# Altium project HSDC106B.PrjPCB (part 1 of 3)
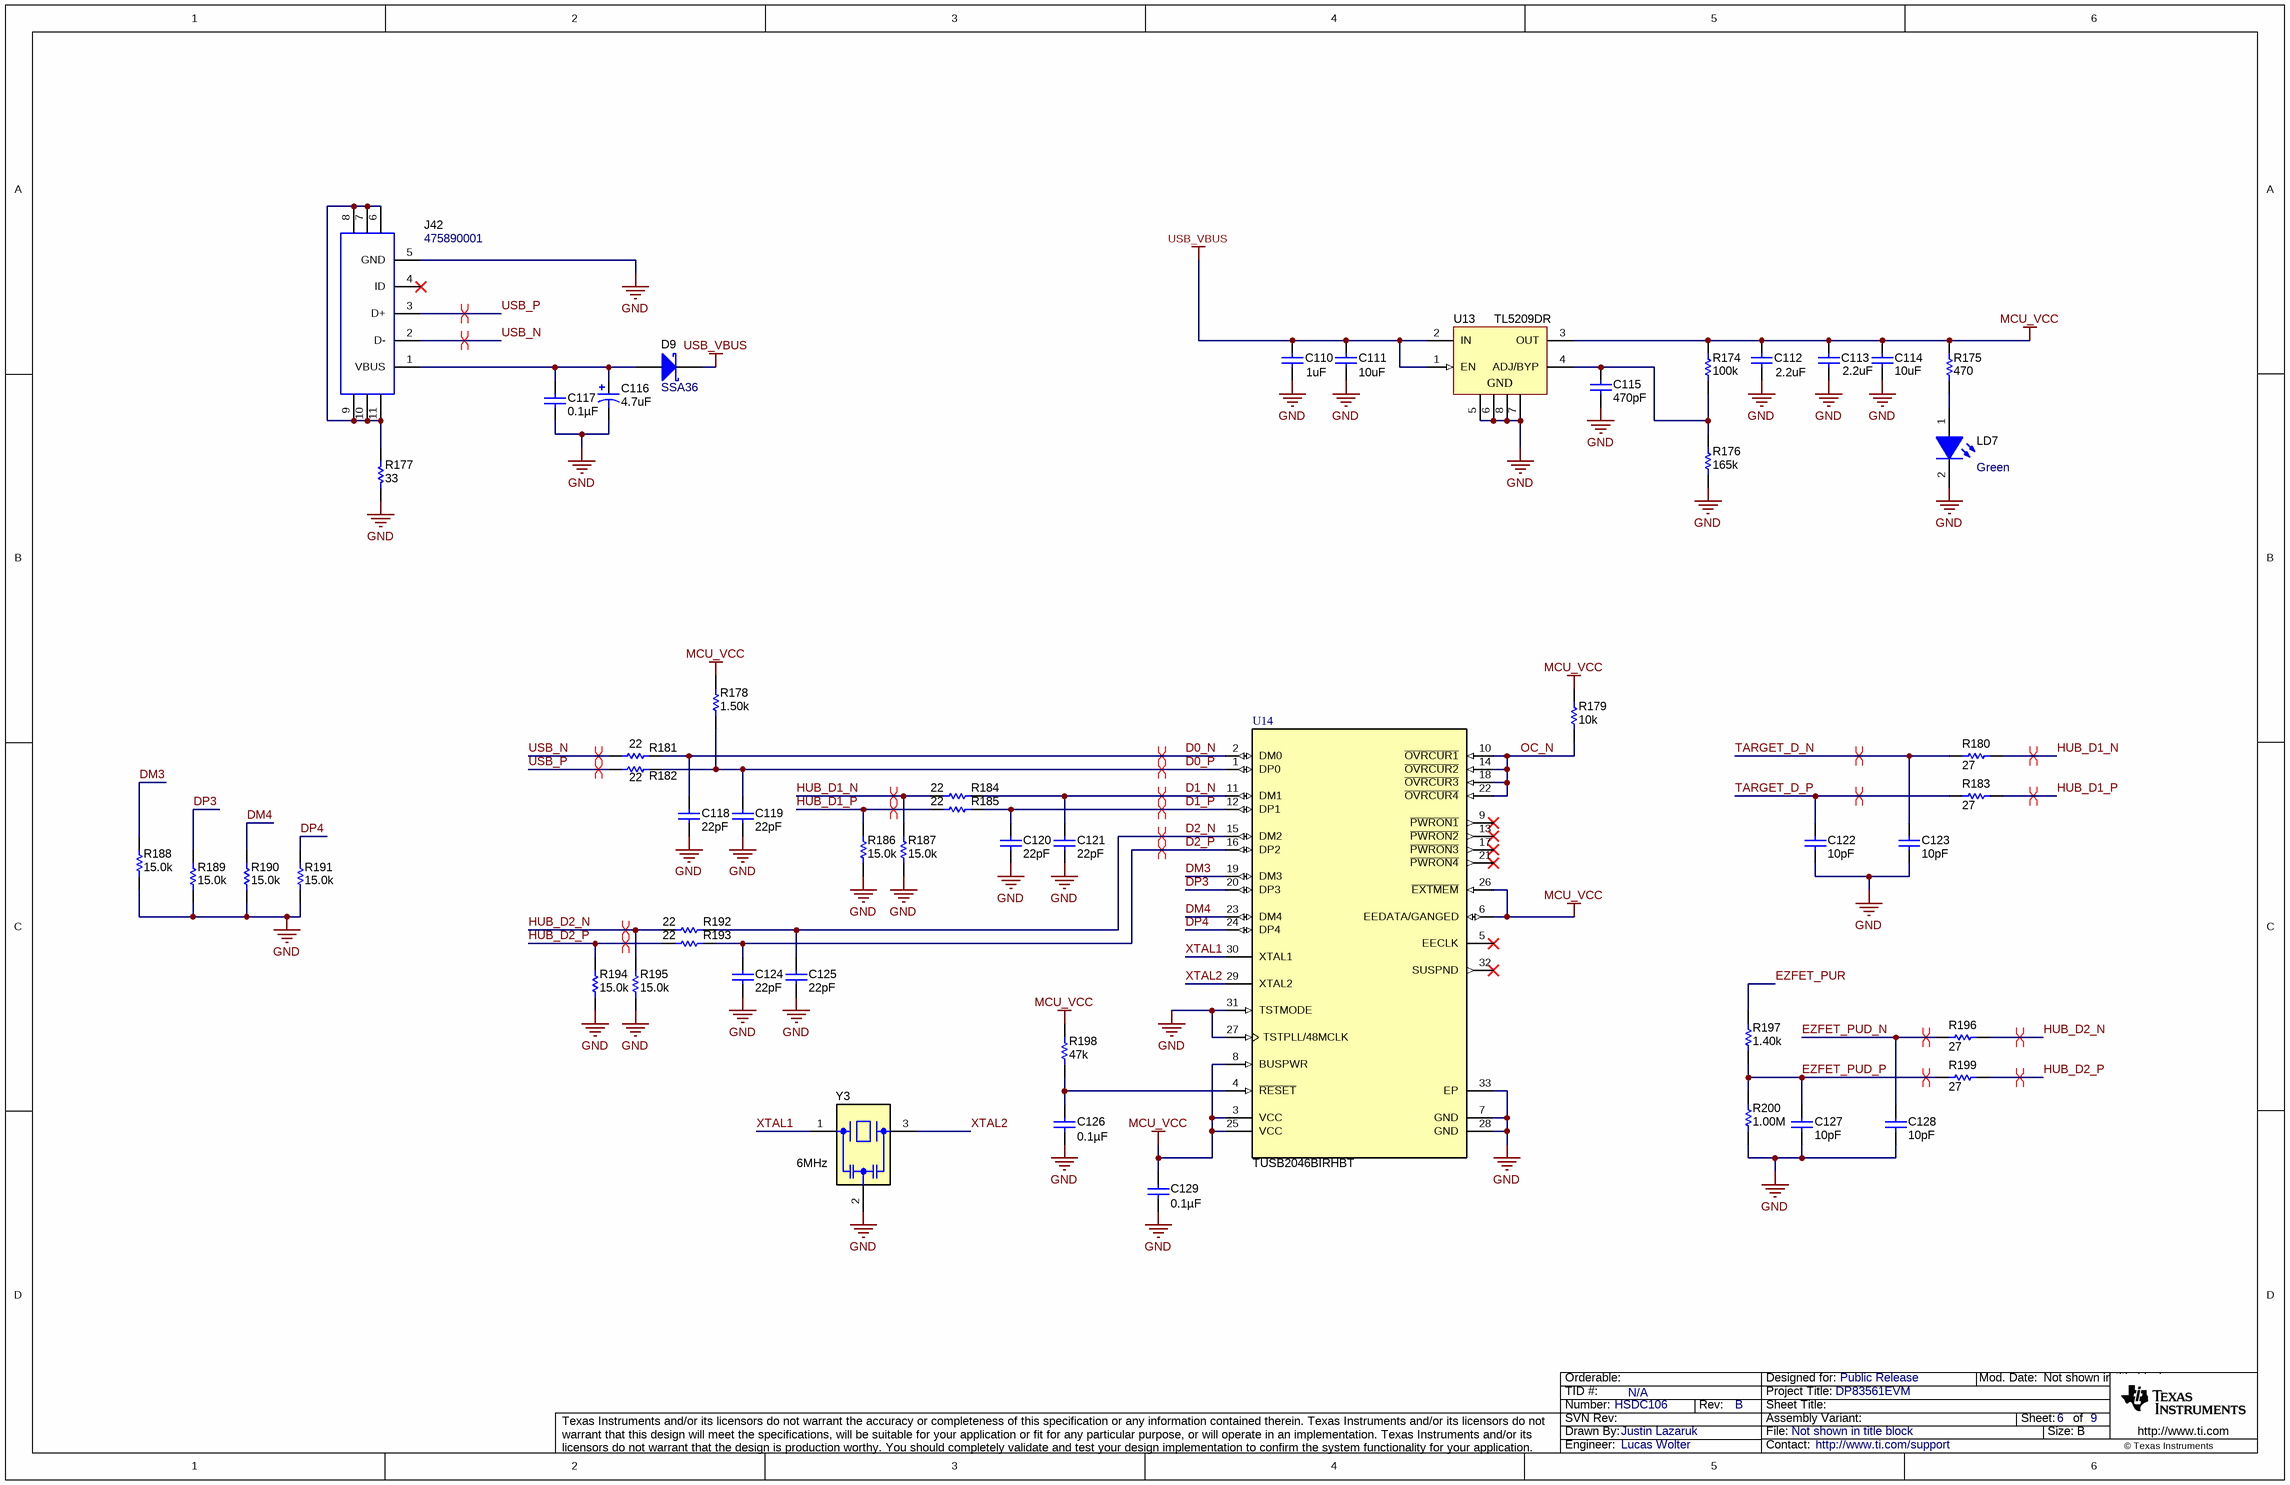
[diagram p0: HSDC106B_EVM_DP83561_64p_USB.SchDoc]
PCB_Layout: Tessolve; PCB_Rev: B; PRJ_Customer: Public Release; PRJ_Engineer: Lucas Wolter; PRJ_Number: HSDC106; PRJ_Title: DP83561EVM; SCH_Rev: B; TechSupport: http://www.ti.com/support; TID: N/A
9 sheets, 472 parts. Net scope: global (net labels, ports and power ports of the same name join across sheets).
Board file: HSDC106B_EVM_DP83561_64p.PcbDoc
Sheets:
  HSDC106B_EVM_DP83561_64p_USB.SchDoc
  HSDC106B_EVM_DP83561_64p_Straps.SchDoc
  HSDC106B_EVM_DP83561_64p_PowerSupply.SchDoc
  HSDC106B_EVM_DP83561_64p_PHY.SchDoc
  HSDC106B_EVM_DP83561_64p_MSP430.SchDoc
  HSDC106B_EVM_DP83561_64p_MAC_RJ45.SchDoc
  HSDC106B_EVM_DP83561_64p_Hardware.SchDoc
  HSDC106B_EVM_DP83561_64p_EZFET.SchDoc
  HSDC106B_EVM_DP83561_64p_Breakout.SchDoc

## Sheet HSDC106B_EVM_DP83561_64p_USB.SchDoc
size 431 x 279 mm; Date: Not shown in title block; ApprovedBy: Not shown in title block; CheckedBy: Not shown in title block; Author: Not shown in title block; CompanyName: Not shown in title block; DrawnBy: Justin Lazaruk; Engineer: Not shown in title block; Organization: Not shown in title block; Address1: Not shown in title block; Address2: Not shown in title block; Address3: Not shown in title block; Address4: Not shown in title block; DocumentNumber: 6; Revision: Use project parameter SCH_Rev; SheetNumber: 6; SheetTotal: 9; PageSetup: Record=PageOptions¦CenterHorizontal=True¦CenterVertical=True¦PrintScale=1.00¦XCorrection=1.00¦YCorrection=1.00¦PrintKind=0¦BorderSize=5000000¦LeftOffset=0¦BottomOffset=0¦Orientation=2¦PaperLength=1000¦PaperWidth=1000¦Scale=100¦PaperSource=15¦PrintQuality=600¦MediaType=1¦DitherType=10¦PaperKind=Letter¦PrintScaleMode=1

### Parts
C110  ValueDisplayed: 1uF  [0402]  (hidden comment: GRM155R6YA105ME11D)
C111  ValueDisplayed: 10uF  [0603]  (hidden comment: GRM188R6YA106MA73D)
C112  ValueDisplayed: 2.2uF  [0402]  (hidden comment: GRM155C81C225KE11D)
C113  ValueDisplayed: 2.2uF  [0402]  (hidden comment: GRM155C81C225KE11D)
C114  ValueDisplayed: 10uF  [0603]  (hidden comment: GRM188R6YA106MA73D)
C115  Cap_F: 470pF  [0603]  (hidden comment: 06031C471JAT2A)
C116  ValueDisplayed: 4.7uF  [7343-31]  (hidden comment: 293D475X9035D2TE3)
C117  ValueDisplayed: 0.1µF  [0402]  (hidden comment: C0402C104K8RACTU)
C118  ValueDisplayed: 22pF  [0402]  (hidden comment: C1005NP01H220J050BA)
C119  ValueDisplayed: 22pF  [0402]  (hidden comment: C1005NP01H220J050BA)
C120  ValueDisplayed: 22pF  [0402]  (hidden comment: C1005NP01H220J050BA)
C121  ValueDisplayed: 22pF  [0402]  (hidden comment: C1005NP01H220J050BA)
C122  Cap_F: 10pF  [0402]  (hidden comment: C0402C100K4GACTU)
C123  Cap_F: 10pF  [0402]  (hidden comment: C0402C100K4GACTU)
C124  ValueDisplayed: 22pF  [0402]  (hidden comment: C1005NP01H220J050BA)
C125  ValueDisplayed: 22pF  [0402]  (hidden comment: C1005NP01H220J050BA)
C126  ValueDisplayed: 0.1µF  [0402]  (hidden comment: CL05B104KO5NNNC)
C127  Cap_F: 10pF  [0402]  (hidden comment: C0402C100K4GACTU)
C128  Cap_F: 10pF  [0402]  (hidden comment: C0402C100K4GACTU)
C129  ValueDisplayed: 0.1µF  [0402]  (hidden comment: CL05B104KO5NNNC)
D9  SSA36  [SMA]
J42  475890001  [Molex_0475890001]
LD7  value Green  [QTLP630C_Green]  (hidden comment: QTLP630C4TR)
R174  ValueDisplayed: 100k  [0402]  (hidden comment: CRCW0402100KDHEDP)
R175  ValueDisplayed: 470  [0402]  (hidden comment: CRCW0402470RJNED)
R176  ValueDisplayed: 165k  [0402]  (hidden comment: CRCW0402165KFKED)
R177  ValueDisplayed: 33  [0402]  (hidden comment: CRCW040233R0JNED)
R178  ValueDisplayed: 1.50k  [0402]  (hidden comment: CRCW04021K50FKED)
R179  ValueDisplayed: 10k  [0402]  (hidden comment: CRCW040210K0JNED)
R180  ValueDisplayed: 27  [0402]  (hidden comment: CRCW040227R0JNED)
R181  ValueDisplayed: 22  [0402]  (hidden comment: CRCW040222R0JNED)
R182  ValueDisplayed: 22  [0402]  (hidden comment: CRCW040222R0JNED)
R183  ValueDisplayed: 27  [0402]  (hidden comment: CRCW040227R0JNED)
R184  ValueDisplayed: 22  [0402]  (hidden comment: CRCW040222R0JNED)
R185  ValueDisplayed: 22  [0402]  (hidden comment: CRCW040222R0JNED)
R186  ValueDisplayed: 15.0k  [0402]  (hidden comment: CRCW040215K0FKED)
R187  ValueDisplayed: 15.0k  [0402]  (hidden comment: CRCW040215K0FKED)
R188  ValueDisplayed: 15.0k  [0402]  (hidden comment: CRCW040215K0FKED)
R189  ValueDisplayed: 15.0k  [0402]  (hidden comment: CRCW040215K0FKED)
R190  ValueDisplayed: 15.0k  [0402]  (hidden comment: CRCW040215K0FKED)
R191  ValueDisplayed: 15.0k  [0402]  (hidden comment: CRCW040215K0FKED)
R192  ValueDisplayed: 22  [0402]  (hidden comment: CRCW040222R0JNED)
R193  ValueDisplayed: 22  [0402]  (hidden comment: CRCW040222R0JNED)
R194  ValueDisplayed: 15.0k  [0402]  (hidden comment: CRCW040215K0FKED)
R195  ValueDisplayed: 15.0k  [0402]  (hidden comment: CRCW040215K0FKED)
R196  ValueDisplayed: 27  [0402]  (hidden comment: CRCW040227R0JNED)
R197  ValueDisplayed: 1.40k  [0402]  (hidden comment: CRCW04021K40FKED)
R198  ValueDisplayed: 47k  [0402]  (hidden comment: CRCW040247K0JNED)
R199  ValueDisplayed: 27  [0402]  (hidden comment: CRCW040227R0JNED)
R200  ValueDisplayed: 1.00M  [0402]  (hidden comment: CRCW04021M00FKED)
U13  TL5209DR  [D0008A_N]
U14  TUSB2046BIRHBT  [RHB0032E]
Y3  Frequency_Fixed: 6MHz  [Murata_CSTCR_G]  (hidden comment: CSTCR6M00G53Z-R0)

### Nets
GND: C110.2 C111.2 C112.2 C113.2 C114.2 C115.2 C116.2(-) C117.1 C118.2 C119.2 C120.2 C121.2 C122.2 C123.2 C124.2 C125.2 C126.2 C127.2 C128.2 C129.2 J42.5(GND) LD7.2(K) R176.1 R177.2 R186.1 R187.1 R188.1 R189.1 R190.1 R191.1 R194.1 R195.1 R200.1 U13.5(GND) U13.6(GND) U13.7(GND) U13.8(GND) U14.7(GND) U14.27(TSTPLL/48MCLK) U14.28(GND) U14.31(TSTMODE) U14.33(EP) Y3.2(GND)
MCU_VCC: C112.1 C113.1 C114.1 C129.1 R174.2 R175.2 R178.2 R179.2 R198.2 U13.3(OUT) U14.3(VCC) U14.6(EEDATA/GANGED) U14.8(BUSPWR) U14.25(VCC) U14.26(~{EXTMEM})
USB_VBUS: C110.1 C111.1 D9.1(K) U13.1(EN) U13.2(IN)
D0_N: C118.1 R181.2 U14.2(DM0)
D0_P: C119.1 R178.1 R182.2 U14.1(DP0)
D1_N: C121.1 R184.2 U14.11(DM1)
D1_P: C120.1 R185.2 U14.12(DP1)
D2_N: C125.1 R192.2 U14.15(DM2)
D2_P: C124.1 R193.2 U14.16(DP2)
DM3: R188.2 U14.19(DM3)
DM4: R190.2 U14.23(DM4)
DP3: R189.2 U14.20(DP3)
DP4: R191.2 U14.24(DP4)
EZFET_PUD_N: C128.1 R196.1
EZFET_PUD_P: C127.1 R197.1 R199.1 R200.2
EZFET_PUR: R197.2
HUB_D1_N: R180.2 R184.1 R187.2
HUB_D1_P: R183.2 R185.1 R186.2
HUB_D2_N: R192.1 R195.2 R196.2
HUB_D2_P: R193.1 R194.2 R199.2
OC_N: R179.1 U14.10(~{OVRCUR1}) U14.14(~{OVRCUR2}) U14.18(~{OVRCUR3}) U14.22(~{OVRCUR4})
TARGET_D_N: C123.1 R180.1
TARGET_D_P: C122.1 R183.1
USB_N: J42.2(D-) R181.1
USB_P: J42.3(D+) R182.1
XTAL1: U14.30(XTAL1) Y3.1(In)
XTAL2: U14.29(XTAL2) Y3.3(Out)
NetC115_1: C115.1 R174.1 R176.2 U13.4(ADJ/BYP)
NetC116_1: C116.1(+) C117.2 D9.2(A) J42.1(VBUS)
NetC126_1: C126.1 R198.1 U14.4(~{RESET})
NetJ42_6: J42.6 J42.7 J42.8 J42.9 J42.10 J42.11 R177.1
NetLD7_1: LD7.1(A) R175.1

Not connected (* = marked no-connect by the designer): J42 4(ID)*; U14 5(EECLK)* 9(~{PWRON1})* 13(~{PWRON2})* 17(~{PWRON3})* 21(~{PWRON4})* 32(SUSPND)*

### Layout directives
differential pair: D0_N, D0_P, D1_N, D1_P, D2_N, D2_P, EZFET_PUD_N, EZFET_PUD_P, HUB_D1_N, HUB_D1_P, HUB_D2_N, HUB_D2_P, TARGET_D_N, TARGET_D_P, USB_N, USB_P

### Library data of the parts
C110 = CMP-0006620-2: CAP, CERM, 1 uF, 35 V, +/- 20%, X5R, 0402; Manufacturer: MuRata; TaMin_C: -55°C; Polarized: N; SizeAreaWB_mm2: 3; Value1: Unknown; U/M: EA; Value: 1uF; TaMax_C: 85°C; SizeZ_mm: 0.6; SizeX_mm: 1; SizeY_mm: 0.5; Value2: 35V; Cap_F: 1µF; AEC Category: Q200
C111 C114 = CMP-0007355-6: CAP, CERM, 10 uF, 35 V, +/- 20%, X5R, 0603; Manufacturer: Murata; TaMin_C: -55°C; Polarized: N; SizeAreaWB_mm2: 4.68; Value1: Unknown; U/M: EA; Value: 10uF; TaMax_C: 85°C; SizeZ_mm: 1; SizeX_mm: 1.6; SizeY_mm: 0.8; Value2: 35V; SizeArea_mm2: 1.28; Cap_F: 10µF; AEC Category: Q200
C112 C113 = CMP-0006526-2: CAP, CERM, 2.2 uF, 16 V, +/- 10%, X6S, 0402; Manufacturer: MuRata; TaMin_C: -55°C; Polarized: N; SizeAreaWB_mm2: 3; Value1: Unknown; U/M: EA; Value: 2.2uF; TaMax_C: 105°C; SizeZ_mm: 0.6; SizeX_mm: 1; SizeY_mm: 0.5; Value2: 16V; Cap_F: 2.2µF; AEC Category: Q200
C115 = CMP-0006743-4: CAP, CERM, 470 pF, 100 V, +/- 5%, X7R, 0603; Manufacturer: AVX; TaMin_C: -55°C; ESR_ohm: 0.397; Polarized: N; SizeAreaWB_mm2: 4.68; Value1: 0.397 ohm; U/M: EA; Value: 470pF; TaMax_C: 125°C; SizeZ_mm: 1; SizeX_mm: 1.6; SizeY_mm: 0.8; Value2: 100V; SizeArea_mm2: 1.28; AEC Category: Q200
C116 = CMP-0011708-2: CAP, TA, 4.7 uF, 35 V, +/- 10%, 1.3 ohm, SMD; Manufacturer: Vishay-Sprague; Polarized: Y; CompType: Capacitor; Value: 4.7uF; U/M: EA; Cap_F: 4.7µF; Value1: 1.3 ohm; VDC_V: 35V; ESR_ohm: 1.3; IRMS_A: 3.4dA; TaMin_C: -55°C; TaMax_C: 125°C; Cap_Case: D; AEC Category: Q200; SizeAreaWB_mm2: 58.59; SizeArea_mm2: 31.39; SizeX_mm: 7.3; SizeY_mm: 4.3; SizeZ_mm: 3.1
C117 = CMP-0078241-1: CAP, CERM, 0.1 µF, 10 V,+/- 10%, X7R, 0402; Manufacturer: Kemet; Polarized: N; Value: 0.1uF; U/M: EA; Cap_F: 100nF; VDC_V: 10V; TaMin_C: -55°C; TaMax_C: 125°C; AEC Category: Q200; SizeArea_mm2: 0.5; SizeAreaWB_mm2: 3; SizeX_mm: 1; SizeZ_mm: 0.6
C118-C121 C124 C125 = CMP-0860896-1: CAP, CERM, 22 pF, 50 V,+/- 5%, C0G/NP0, 0402; Manufacturer: TDK; SizeAreaWB_mm2: 3; SizeX_mm: 1; Polarized: N; Value2: 50V; AEC Category: Q200; TaMin_C: -55°C; SizeArea_mm2: 0.5; U/M: EA; SizeZ_mm: 0.6; TaMax_C: 150°C; Value: 22pF
C122 C123 C127 C128 = CMP-0079539-1: CAP, CERM, 10 pF, 16 V,+/- 10%, C0G, 0402; Manufacturer: Kemet; SizeAreaWB_mm2: 3; SizeArea_mm2: 0.5; AEC Qualified: N; AEC Category: Q200; Value: 10pF; TaMax_C: 125°C; SizeZ_mm: 0.6; Green_REACh: Passed; TaMin_C: -55°C; Value2: 16V; Green_Lifecycle: Active; U/M: EA; SizeX_mm: 1
C126 C129 = CMP-0085850-1: CAP, CERM, 0.1 µF, 16 V,+/- 10%, X7R, 0402; Manufacturer: Walsin; SizeZ_mm: 0.6; SizeX_mm: 1; AEC Category: Q200; AEC Qualified: N; SizeY_mm: 0.5; VDC_V: 16V; Value: 0.1uF; Cap_F: 100nF; U/M: EA; SizeAreaWB_mm2: 3; TaMin_C: -55°C; TaMax_C: 125°C
D9 = CMP-0028810-2: Diode, Schottky, 60 V, 3 A, AEC-Q101, SMA; Manufacturer: Fairchild Semiconductor; Value: 60V; SizeArea_mm2: 16.3228; Value1: 3A; AEC Qualified: Y; SizeZ_mm: 2.87; Green_REACh: Incomplete; Value2: 0.75V; Vf_V: 750mV; SizeAreaWB_mm2: 37.3428; SizeX_mm: 5.59; Green_Lifecycle: Not Set; TJmax_C: 150°C; SizeY_mm: 2.92; AEC Category: Q101
J42 = CMP-0055301-1: Connector, Receptacle, Micro-USB Type AB, R/A, Bottom Mount SMT; Manufacturer: Molex; CNHeader: FALSE; Green_Lifecycle: Active; Gender: Female; Green_REACh: Passed; CompType: USB; CT: TRUE
LD7 = CMP-0002917-2: LED, Green, SMD; Manufacturer: Everlight; Vf_V: 2.1V; Io_A: 20mA; Vr_V: 5V; Tjmax_C: 85°C; Value1: W; Angle: 140
R174 = CMP-0026768-2: RES, 100 k, 0.5%, 0.063 W, AEC-Q200 Grade 0, 0402; Manufacturer: Vishay-Dale; Power_W: 63mW; TempCo: 50 ppm/C; Value: 100k; EIA_Code: E192; SizeX_mm: 1; SizeY_mm: 0.5; SizeZ_mm: 0.6; Value2: 0.063W; AEC Qualified: Y; VDC_V: 50V; AEC Category: Q200; AEC Grade: 0
R175 = CMP-0026934-3: RES, 470, 5%, 0.063 W, AEC-Q200 Grade 0, 0402; Manufacturer: Vishay-Dale; Power_W: 63mW; TempCo: 200 ppm/C; Value_Code: 470R; Value: 470; EIA_Code: E24; SizeX_mm: 1; SizeY_mm: 0.5; SizeZ_mm: 0.6; Value2: 0.063W; AEC Qualified: Y; VDC_V: 50V; AEC Category: Q200; AEC Grade: 0
R176 = CMP-0026036-3: RES, 165 k, 1%, 0.063 W, AEC-Q200 Grade 0, 0402; Manufacturer: Vishay-Dale; Power_W: 63mW; TempCo: 100 ppm/C; Value: 165k; EIA_Code: E96; SizeX_mm: 1; SizeY_mm: 0.5; SizeZ_mm: 0.6; Value2: 0.063W; AEC Qualified: Y; VDC_V: 50V; AEC Category: Q200; AEC Grade: 0
R177 = CMP-0026908-3: RES, 33, 5%, 0.063 W, AEC-Q200 Grade 0, 0402; Manufacturer: Vishay-Dale; Value: 33; Value_Code: 33R0; Power_W: 63mW; Value2: 0.063W; VDC_V: 50V; TempCo: 200 ppm/C; EIA_Code: E24; AEC Category: Q200; AEC Qualified: Y; AEC Grade: 0; SizeArea_mm2: 0.5; SizeX_mm: 1; SizeZ_mm: 0.6
R178 = CMP-0026088-3: RES, 1.50 k, 1%, 0.063 W, AEC-Q200 Grade 0, 0402; Manufacturer: Vishay-Dale; Power_W: 63mW; TempCo: 100 ppm/C; Value_Code: 1k50; Value: 1.50k; EIA_Code: E96; Res_ohm: 1.5k; SizeX_mm: 1; SizeY_mm: 0.5; SizeZ_mm: 0.6; Value2: 0.063W; AEC Qualified: Y; VDC_V: 50V; AEC Category: Q200; AEC Grade: 0
R179 = CMP-0026825-5: RES, 10 k, 5%, 0.063 W, AEC-Q200 Grade 0, 0402; Manufacturer: Vishay-Dale; Power_W: 63mW; TempCo: 200 ppm/C; Value_Code: 10k0; Value: 10k; EIA_Code: E24; SizeX_mm: 1; SizeY_mm: 0.5; SizeZ_mm: 0.6; Value2: 0.063W; AEC Qualified: Y; VDC_V: 50V; AEC Category: Q200; AEC Grade: 0
R180 R183 = CMP-0026888-3: RES, 27, 5%, 0.063 W, AEC-Q200 Grade 0, 0402; Manufacturer: Vishay-Dale; Value: 27; Value_Code: 27R0; Power_W: 63mW; Value2: 0.063W; VDC_V: 50V; TempCo: 200 ppm/C; EIA_Code: E24; AEC Category: Q200; AEC Qualified: Y; AEC Grade: 0; SizeArea_mm2: 0.5; SizeX_mm: 1; SizeZ_mm: 0.6
R181 R182 R184 R185 R192 R193 = CMP-0026880-3: RES, 22, 5%, 0.063 W, AEC-Q200 Grade 0, 0402; Manufacturer: Vishay-Dale; Power_W: 63mW; TempCo: 200 ppm/C; Value_Code: 22R0; Value: 22; EIA_Code: E24; SizeX_mm: 1; SizeY_mm: 0.5; SizeZ_mm: 0.6; Value2: 0.063W; AEC Qualified: Y; VDC_V: 50V; AEC Category: Q200; AEC Grade: 0
R186-R191 R194 R195 = CMP-0026027-3: RES, 15.0 k, 1%, 0.063 W, AEC-Q200 Grade 0, 0402; Manufacturer: Vishay-Dale; Power_W: 63mW; TempCo: 100 ppm/C; Value_Code: 15k0; Value: 15.0k; EIA_Code: E96; Res_ohm: 15k; SizeX_mm: 1; SizeY_mm: 0.5; SizeZ_mm: 0.6; Value2: 0.063W; AEC Qualified: Y; VDC_V: 50V; AEC Category: Q200; AEC Grade: 0
R196 R199 = CMP-0026888-3: RES, 27, 5%, 0.063 W, AEC-Q200 Grade 0, 0402; Manufacturer: Vishay-Dale; Power_W: 63mW; TempCo: 200 ppm/C; Value_Code: 27R0; Value: 27; EIA_Code: E24; SizeX_mm: 1; SizeY_mm: 0.5; SizeZ_mm: 0.6; Value2: 0.063W; AEC Qualified: Y; VDC_V: 50V; AEC Category: Q200; AEC Grade: 0
R197 = CMP-0026085-3: RES, 1.40 k, 1%, 0.063 W, AEC-Q200 Grade 0, 0402; Manufacturer: Vishay-Dale; Power_W: 63mW; TempCo: 100 ppm/C; Value_Code: 1k40; Value: 1.40k; EIA_Code: E96; Res_ohm: 1.4k; SizeX_mm: 1; SizeY_mm: 0.5; SizeZ_mm: 0.6; Value2: 0.063W; AEC Qualified: Y; VDC_V: 50V; AEC Category: Q200; AEC Grade: 0
R198 = CMP-0026935-3: RES, 47 k, 5%, 0.063 W, AEC-Q200 Grade 0, 0402; Manufacturer: Vishay-Dale; Power_W: 63mW; TempCo: 200 ppm/C; Value_Code: 47k0; Value: 47k; EIA_Code: E24; SizeX_mm: 1; SizeY_mm: 0.5; SizeZ_mm: 0.6; Value2: 0.063W; AEC Qualified: Y; VDC_V: 50V; AEC Category: Q200; AEC Grade: 0
R200 = CMP-0026100-2: RES, 1.00 M, 1%, 0.063 W, AEC-Q200 Grade 0, 0402; Manufacturer: Vishay-Dale; Power_W: 63mW; TempCo: 100 ppm/C; Value_Code: 1M00; Value: 1.00Meg; EIA_Code: E96; Res_ohm: 1M; SizeX_mm: 1; SizeY_mm: 0.5; SizeZ_mm: 0.6; Value2: 0.063W; AEC Qualified: Y; VDC_V: 50V; AEC Category: Q200; AEC Grade: 0
U13 = CMP-0036447-1: Single Output Low Noise LDO, 500 mA, Adjustable 1.3 to 6.5 V Output, 2.5 to 16 V Input, 8-pin SOIC (D), -40 to 125 degC, Green (RoHS & no Sb/Br); Manufacturer: Texas Instruments; Iq(Typ)(mA): 8; Accuracy(%): 2; Vdo(Typ)(mV): 500; Iout(Max)(A): 0.5; Vin(Max)(V): 16; Vout Adj(Min)(V): 2.5; Vout Adj(Max)(V): 6.5; SubFamily: Single Channel LDO; Rating: Catalog
U14 = CMP-0033743-2: 4-Port Full-Speed USB Hub, 3.3V, -40 to 85 degC, 32-Pin QFN (RHB), Green (RoHS & no Sb/Br); Manufacturer: Texas Instruments; SubFamily: USB Hub Controller; Supply Voltage(s)(V): 3.3; USB Speed: Full; USB Full Speed: True
Y3 = CMP-0006147-4: Resonator, 6 MHz, 15pF SMD; Manufacturer: MuRata; TaMin_C: -40°C; Frequency Stability: +/-0.2 %; TaMax_C: 125°C; AEC Category: Q200; AEC Qualified: N

## Sheet HSDC106B_EVM_DP83561_64p_Straps.SchDoc
size 431 x 279 mm; Date: Not shown in title block; ApprovedBy: Not shown in title block; CheckedBy: Not shown in title block; Author: Not shown in title block; CompanyName: Not shown in title block; DrawnBy: Justin Lazaruk; Engineer: Not shown in title block; Organization: Not shown in title block; Address1: Not shown in title block; Address2: Not shown in title block; Address3: Not shown in title block; Address4: Not shown in title block; DocumentNumber: 3; Revision: Use project parameter SCH_Rev; SheetNumber: 3; SheetTotal: 9; PageSetup: Record=PageOptions¦CenterHorizontal=True¦CenterVertical=True¦PrintScale=1.00¦XCorrection=1.00¦YCorrection=1.00¦PrintKind=0¦BorderSize=5000000¦LeftOffset=0¦BottomOffset=0¦Orientation=2¦PaperLength=1000¦PaperWidth=1000¦Scale=100¦PaperSource=15¦PrintQuality=600¦MediaType=1¦DitherType=10¦PaperKind=Letter¦PrintScaleMode=1
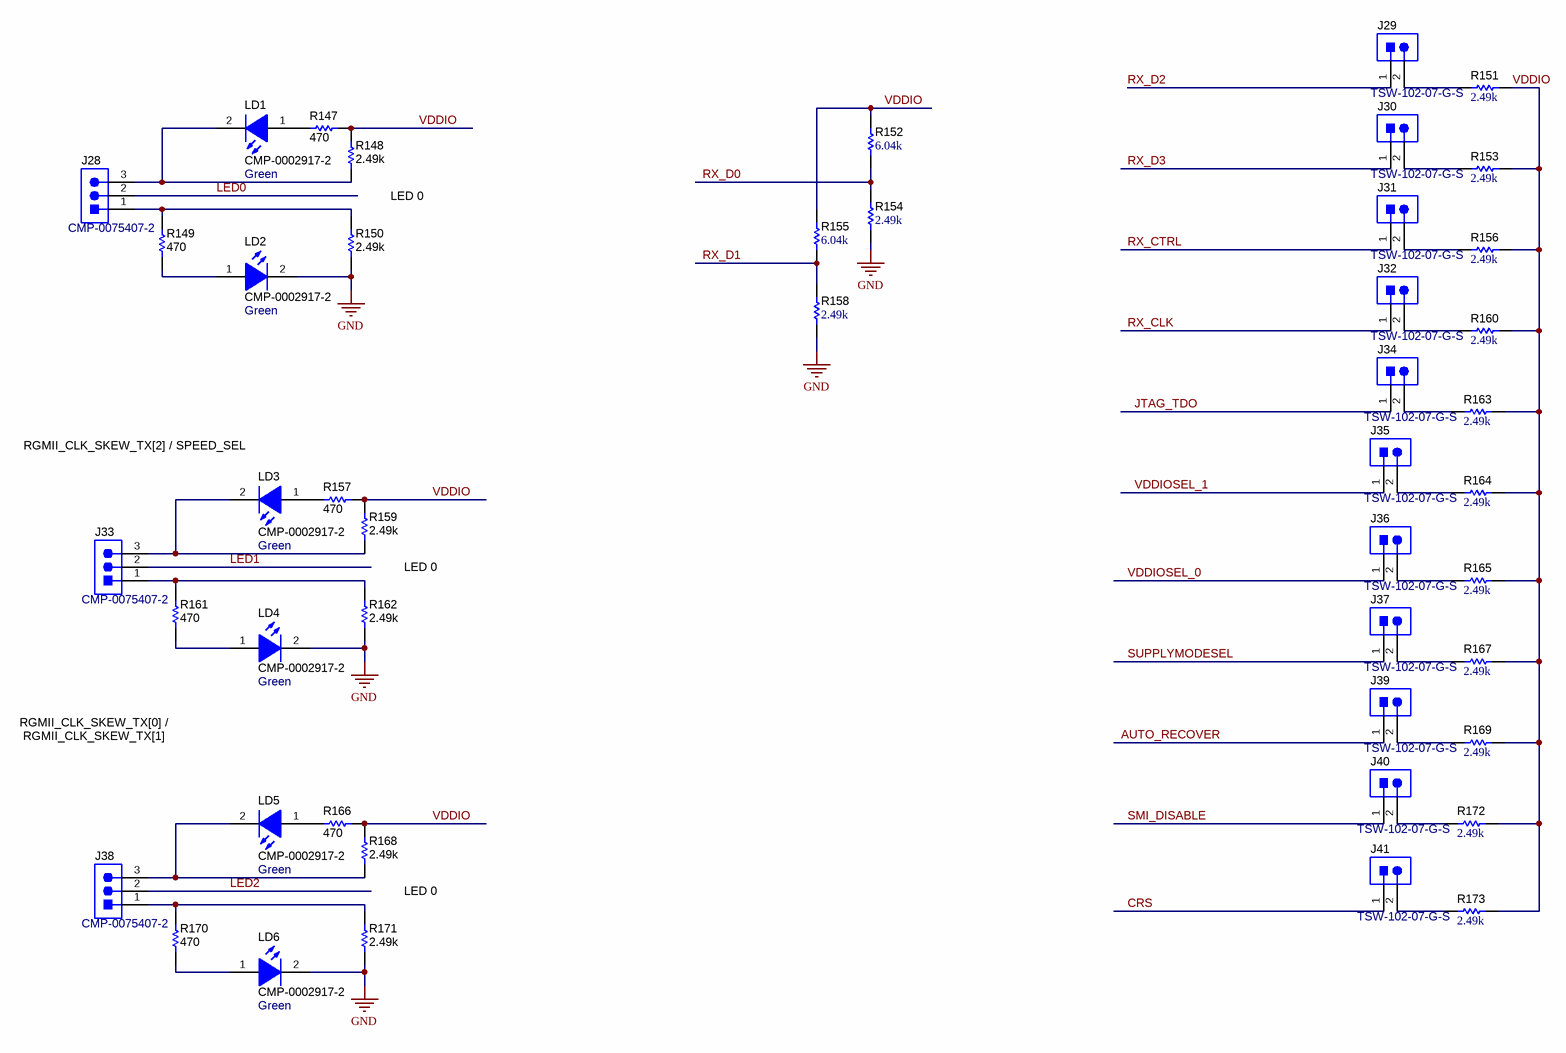
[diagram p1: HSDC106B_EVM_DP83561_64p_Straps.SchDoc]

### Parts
J28  CMP-0075407-2  [TSW-103-07-G-S]
J29  TSW-102-07-G-S  [TSW-102-07-G-S]
J30  TSW-102-07-G-S  [TSW-102-07-G-S]
J31  TSW-102-07-G-S  [TSW-102-07-G-S]
J32  TSW-102-07-G-S  [TSW-102-07-G-S]
J33  CMP-0075407-2  [TSW-103-07-G-S]
J34  TSW-102-07-G-S  [TSW-102-07-G-S]
J35  TSW-102-07-G-S  [TSW-102-07-G-S]
J36  TSW-102-07-G-S  [TSW-102-07-G-S]
J37  TSW-102-07-G-S  [TSW-102-07-G-S]
J38  CMP-0075407-2  [TSW-103-07-G-S]
J39  TSW-102-07-G-S  [TSW-102-07-G-S]
J40  TSW-102-07-G-S  [TSW-102-07-G-S]
J41  TSW-102-07-G-S  [TSW-102-07-G-S]
LD1  CMP-0002917-2  value Green  [QTLP630C_Green]
LD2  CMP-0002917-2  value Green  [QTLP630C_Green]
LD3  CMP-0002917-2  value Green  [QTLP630C_Green]
LD4  CMP-0002917-2  value Green  [QTLP630C_Green]
LD5  CMP-0002917-2  value Green  [QTLP630C_Green]
LD6  CMP-0002917-2  value Green  [QTLP630C_Green]
R147  ValueDisplayed: 470  [0402]  (hidden comment: CRCW0402470RJNED)
R148  ValueDisplayed: 2.49k  [0402]  (hidden comment: CRCW04022K49FKED)
R149  ValueDisplayed: 470  [0402]  (hidden comment: CRCW0402470RJNED)
R150  ValueDisplayed: 2.49k  [0402]  (hidden comment: CRCW04022K49FKED)
R151  ValueDisplayed: 2.49k  [0402]  (hidden comment: CRCW04022K49FKED)
R152  ValueDisplayed: 6.04k  [0402]  (hidden comment: CRCW04026K04FKED)
R153  ValueDisplayed: 2.49k  [0402]  (hidden comment: CRCW04022K49FKED)
R154  ValueDisplayed: 2.49k  [0402]  (hidden comment: CRCW04022K49FKED)
R155  ValueDisplayed: 6.04k  [0402]  (hidden comment: CRCW04026K04FKED)
R156  ValueDisplayed: 2.49k  [0402]  (hidden comment: CRCW04022K49FKED)
R157  ValueDisplayed: 470  [0402]  (hidden comment: CRCW0402470RJNED)
R158  ValueDisplayed: 2.49k  [0402]  (hidden comment: CRCW04022K49FKED)
R159  ValueDisplayed: 2.49k  [0402]  (hidden comment: CRCW04022K49FKED)
R160  ValueDisplayed: 2.49k  [0402]  (hidden comment: CRCW04022K49FKED)
R161  ValueDisplayed: 470  [0402]  (hidden comment: CRCW0402470RJNED)
R162  ValueDisplayed: 2.49k  [0402]  (hidden comment: CRCW04022K49FKED)
R163  ValueDisplayed: 2.49k  [0402]  (hidden comment: CRCW04022K49FKED)
R164  ValueDisplayed: 2.49k  [0402]  (hidden comment: CRCW04022K49FKED)
R165  ValueDisplayed: 2.49k  [0402]  (hidden comment: CRCW04022K49FKED)
R166  ValueDisplayed: 470  [0402]  (hidden comment: CRCW0402470RJNED)
R167  ValueDisplayed: 2.49k  [0402]  (hidden comment: CRCW04022K49FKED)
R168  ValueDisplayed: 2.49k  [0402]  (hidden comment: CRCW04022K49FKED)
R169  ValueDisplayed: 2.49k  [0402]  (hidden comment: CRCW04022K49FKED)
R170  ValueDisplayed: 470  [0402]  (hidden comment: CRCW0402470RJNED)
R171  ValueDisplayed: 2.49k  [0402]  (hidden comment: CRCW04022K49FKED)
R172  ValueDisplayed: 2.49k  [0402]  (hidden comment: CRCW04022K49FKED)
R173  ValueDisplayed: 2.49k  [0402]  (hidden comment: CRCW04022K49FKED)

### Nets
GND: LD2.2(K) LD4.2(K) LD6.2(K) R150.1 R154.1 R158.1 R162.1 R171.1
VDDIO: R147.1 R148.2 R151.2 R152.2 R153.2 R155.2 R156.2 R157.1 R159.2 R160.2 R163.2 R164.2 R165.2 R166.1 R167.2 R168.2 R169.2 R172.2 R173.2
AUTO_RECOVER: J39.1
CRS: J41.1
JTAG_TDO: J34.1
LED0: J28.2
LED1: J33.2
LED2: J38.2
RX_CLK: J32.1
RX_CTRL: J31.1
RX_D0: R152.1 R154.2
RX_D1: R155.1 R158.2
RX_D2: J29.1
RX_D3: J30.1
SMI_DISABLE: J40.1
SUPPLYMODESEL: J37.1
VDDIOSEL_0: J36.1
VDDIOSEL_1: J35.1
NetJ28_1: J28.1 R149.2 R150.2
NetJ28_3: J28.3 LD1.2(K) R148.1
NetJ29_2: J29.2 R151.1
NetJ30_2: J30.2 R153.1
NetJ31_2: J31.2 R156.1
NetJ32_2: J32.2 R160.1
NetJ33_1: J33.1 R161.2 R162.2
NetJ33_3: J33.3 LD3.2(K) R159.1
NetJ34_2: J34.2 R163.1
NetJ35_2: J35.2 R164.1
NetJ36_2: J36.2 R165.1
NetJ37_2: J37.2 R167.1
NetJ38_1: J38.1 R170.2 R171.2
NetJ38_3: J38.3 LD5.2(K) R168.1
NetJ39_2: J39.2 R169.1
NetJ40_2: J40.2 R172.1
NetJ41_2: J41.2 R173.1
NetLD1_1: LD1.1(A) R147.2
NetLD2_1: LD2.1(A) R149.1
NetLD3_1: LD3.1(A) R157.2
NetLD4_1: LD4.1(A) R161.1
NetLD5_1: LD5.1(A) R166.2
NetLD6_1: LD6.1(A) R170.1

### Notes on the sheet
- LED 0
- RGMII_CLK_SKEW_TX[2] / SPEED_SEL
- RGMII_CLK_SKEW_TX[0] /
- RGMII_CLK_SKEW_TX[1]

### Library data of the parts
J28 J33 J38 = CMP-0075407-2: Header, 100mil, 3x1, Gold, TH; Manufacturer: Samtec; Pitch_mm: 2.54; Gender: Male; Shrouded: N; Row_Count: 1; Current_A: 6.3A; Voltage_V: 550V; Cert_CSA: Y; Green_REACh: Passed; Green_Lifecycle: Active
J29-J32 J34-J37 J39-J41 = CMP-0075405-3: Header, 100mil, 2x1, Gold, TH; Manufacturer: Samtec; Pitch_mm: 2.54; Gender: Male; Shrouded: N; Row_Count: 1; Current_A: 6.3A; Voltage_V: 550V; Cert_CSA: Y; Green_REACh: Passed; Green_Lifecycle: Active
LD1-LD6 = CMP-0002917-2: LED, Green, SMD; PartNumber: QTLP630C4TR; Manufacturer: Everlight; Vf_V: 2.1V; Io_A: 20mA; Vr_V: 5V; Tjmax_C: 85°C; Value1: W; Angle: 140
R147 R149 R157 R161 R166 R170 = CMP-0026934-3: RES, 470, 5%, 0.063 W, AEC-Q200 Grade 0, 0402; Manufacturer: Vishay-Dale; Value: 470; Value_Code: 470R; Power_W: 63mW; Value2: 0.063W; VDC_V: 50V; TempCo: 200 ppm/C; EIA_Code: E24; AEC Category: Q200; AEC Grade: 0; AEC Qualified: Y; SizeArea_mm2: 0.5; SizeX_mm: 1; SizeZ_mm: 0.6
R148 R150 R159 R162 R168 R171 = CMP-0026237-2: RES, 2.49 k, 1%, 0.063 W, AEC-Q200 Grade 0, 0402; Manufacturer: Vishay-Dale; Value: 2.49k; Value_Code: 2k49; Power_W: 63mW; Value2: 0.063W; VDC_V: 50V; TempCo: 100 ppm/C; EIA_Code: E96; AEC Category: Q200; AEC Grade: 0; AEC Qualified: Y; SizeArea_mm2: 0.5; SizeX_mm: 1; SizeZ_mm: 0.6
R151 R153 R154 R156 R158 R160 R163-R165 R167 R169 R172 R173 = CMP-0026237-2: RES, 2.49 k, 1%, 0.063 W, AEC-Q200 Grade 0, 0402; Manufacturer: Vishay-Dale; Power_W: 63mW; TempCo: 100 ppm/C; Value_Code: 2k49; Value: 2.49k; EIA_Code: E96; SizeX_mm: 1; SizeY_mm: 0.5; SizeZ_mm: 0.6; Value2: 0.063W; AEC Qualified: Y; VDC_V: 50V; AEC Grade: 0; AEC Category: Q200
R152 R155 = CMP-0026512-2: RES, 6.04 k, 1%, 0.063 W, AEC-Q200 Grade 0, 0402; Manufacturer: Vishay-Dale; Power_W: 63mW; TempCo: 100 ppm/C; Value_Code: 6k04; Value: 6.04k; EIA_Code: E96; SizeX_mm: 1; SizeY_mm: 0.5; SizeZ_mm: 0.6; Value2: 0.063W; AEC Qualified: Y; VDC_V: 50V; AEC Grade: 0; AEC Category: Q200

## Sheet HSDC106B_EVM_DP83561_64p_PowerSupply.SchDoc
size 431 x 279 mm; Date: Not shown in title block; ApprovedBy: Not shown in title block; CheckedBy: Not shown in title block; Author: Not shown in title block; CompanyName: Not shown in title block; DrawnBy: Justin Lazaruk; Engineer: Not shown in title block; Organization: Not shown in title block; Address1: Not shown in title block; Address2: Not shown in title block; Address3: Not shown in title block; Address4: Not shown in title block; DocumentNumber: 1; Revision: Use project parameter SCH_Rev; SheetNumber: 1; SheetTotal: 9; PageSetup: Record=PageOptions¦CenterHorizontal=True¦CenterVertical=True¦PrintScale=1.00¦XCorrection=1.00¦YCorrection=1.00¦PrintKind=0¦BorderSize=5000000¦LeftOffset=0¦BottomOffset=0¦Orientation=2¦PaperLength=1000¦PaperWidth=1000¦Scale=100¦PaperSource=15¦PrintQuality=600¦MediaType=1¦DitherType=10¦PaperKind=Letter¦PrintScaleMode=1
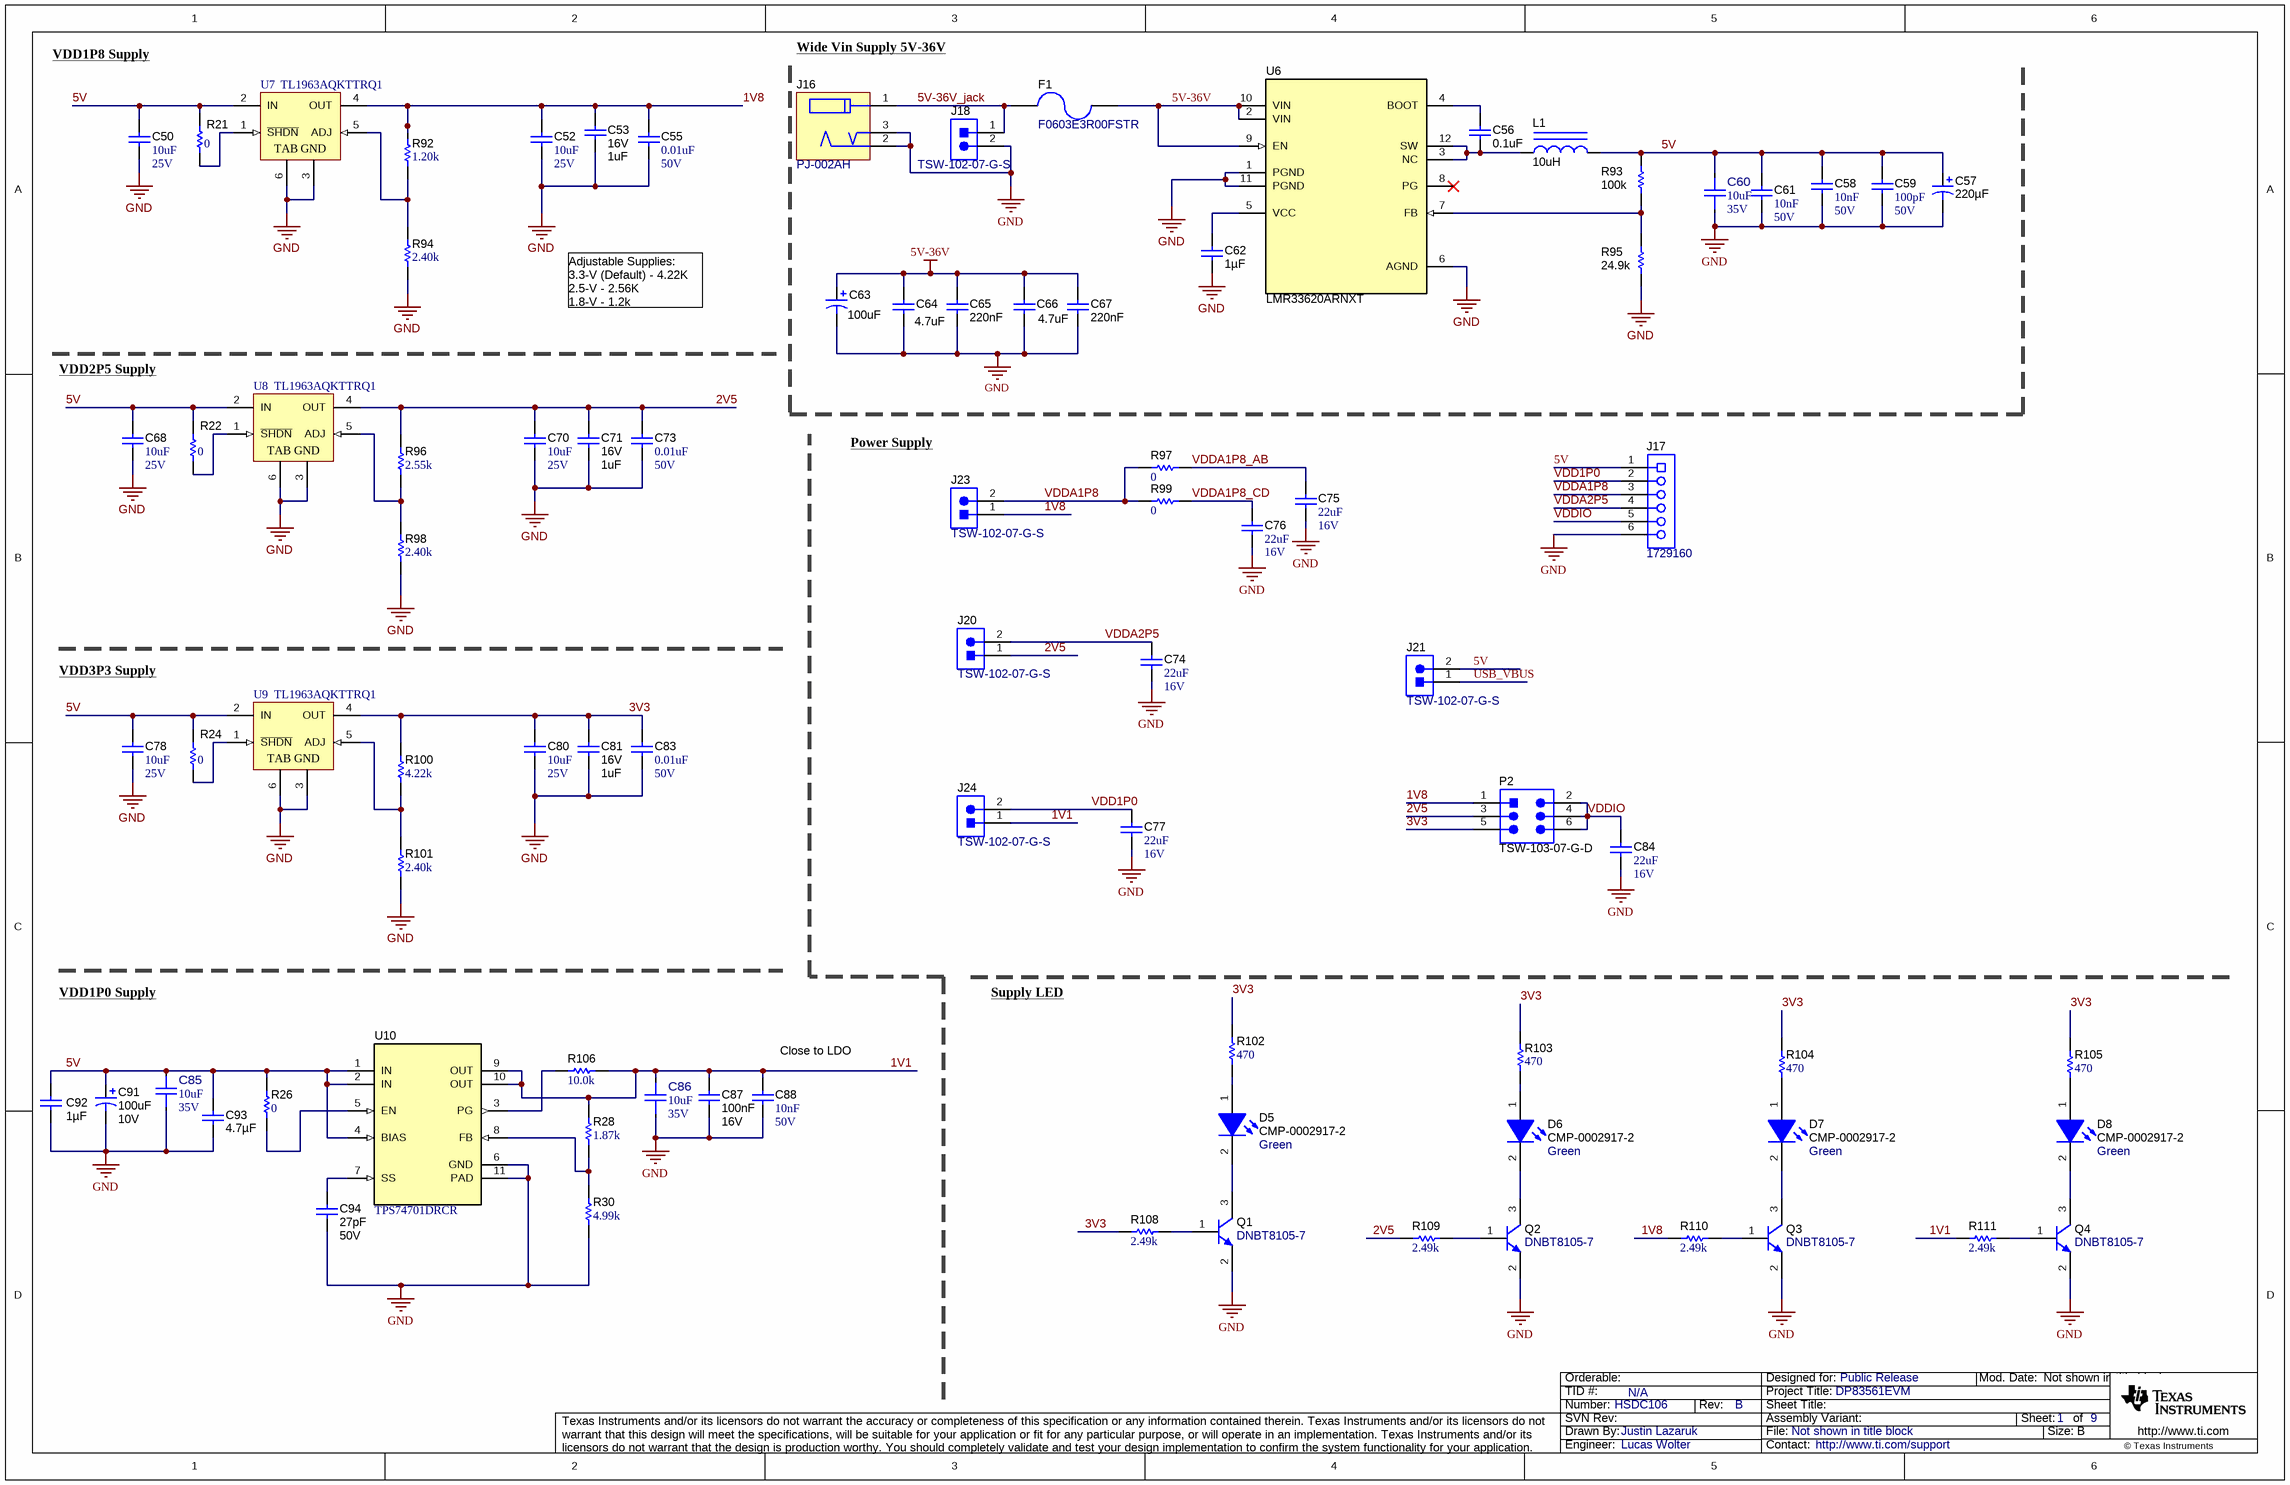
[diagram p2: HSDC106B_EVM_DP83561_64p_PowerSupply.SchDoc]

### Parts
C50  ValueDisplayed: 10uF  VDC_V: 25V  [1210_280]  (hidden comment: CMP-0009155-2)
C52  ValueDisplayed: 10uF  VDC_V: 25V  [1210_280]  (hidden comment: CMP-0009155-2)
C53  VDC_V: 16V  ValueDisplayed: 1uF  [0805_HV]  (hidden comment: 0805YD105KAT2A)
C55  ValueDisplayed: 0.01uF  VDC_V: 50V  [0402]  (hidden comment: CMP-0006324-2)
C56  ValueDisplayed: 0.1uF  [0402]  (hidden comment: GCM155R71H104KE02D)
C57  ValueDisplayed: 220µF  [7343-31]  (hidden comment: T491D227K006AT)
C58  Cap_F: 10nF  VDC_V: 50V  [0603]  (hidden comment: CMP-0006850-4)
C59  ValueDisplayed: 100pF  VDC_V: 50V  [0402]  (hidden comment: CMP-0006303-2)
C60  ValueDisplayed: 10uF  VDC_V: 35V  [FP-GMJ316BB7106MLHT_1206-MFG]  (hidden comment: GMJ316BB7106MLHT)
C61  Cap_F: 10nF  VDC_V: 50V  [0603]  (hidden comment: CMP-0006850-4)
C62  Cap_F: 1µF  [0603]  (hidden comment: CGA3E1X7R1V105K080AC)
C63  ValueDisplayed: 100uF  [CAPSMT_62_HA0]  (hidden comment: EMVE500ADA101MHA0G)
C64  ValueDisplayed: 4.7uF  [1210_280]  (hidden comment: CGA6P3X7R1H475K250AB)
C65  Cap_F: 220nF  [0603]  (hidden comment: CGA3E3X7R1H224K080AB)
C66  ValueDisplayed: 4.7uF  [1210_280]  (hidden comment: CGA6P3X7R1H475K250AB)
C67  Cap_F: 220nF  [0603]  (hidden comment: CGA3E3X7R1H224K080AB)
C68  ValueDisplayed: 10uF  VDC_V: 25V  [1210_280]  (hidden comment: CMP-0009155-2)
C70  ValueDisplayed: 10uF  VDC_V: 25V  [1210_280]  (hidden comment: CMP-0009155-2)
C71  VDC_V: 16V  ValueDisplayed: 1uF  [0805_HV]  (hidden comment: 0805YD105KAT2A)
C73  ValueDisplayed: 0.01uF  VDC_V: 50V  [0402]  (hidden comment: CMP-0006324-2)
C74  ValueDisplayed: 22uF  VDC_V: 16V  [1210_280]  (hidden comment: CMP-0009154-2)
C75  ValueDisplayed: 22uF  VDC_V: 16V  [1210_280]  (hidden comment: CMP-0009154-2)
C76  ValueDisplayed: 22uF  VDC_V: 16V  [1210_280]  (hidden comment: CMP-0009154-2)
C77  ValueDisplayed: 22uF  VDC_V: 16V  [1210_280]  (hidden comment: CMP-0009154-2)
C78  ValueDisplayed: 10uF  VDC_V: 25V  [1210_280]  (hidden comment: CMP-0009155-2)
C80  ValueDisplayed: 10uF  VDC_V: 25V  [1210_280]  (hidden comment: CMP-0009155-2)
C81  VDC_V: 16V  ValueDisplayed: 1uF  [0805_HV]  (hidden comment: 0805YD105KAT2A)
C83  ValueDisplayed: 0.01uF  VDC_V: 50V  [0402]  (hidden comment: CMP-0006324-2)
C84  ValueDisplayed: 22uF  VDC_V: 16V  [1210_280]  (hidden comment: CMP-0009154-2)
C85  ValueDisplayed: 10uF  VDC_V: 35V  [FP-GMJ316BB7106MLHT_1206-MFG]  (hidden comment: GMJ316BB7106MLHT)
C86  ValueDisplayed: 10uF  VDC_V: 35V  [FP-GMJ316BB7106MLHT_1206-MFG]  (hidden comment: GMJ316BB7106MLHT)
C87  Cap_F: 100nF  VDC_V: 16V  [0603]  (hidden comment: CL10B104KO8NNNC)
C88  Cap_F: 10nF  VDC_V: 50V  [0603]  (hidden comment: CMP-0006850-4)
C91  ValueDisplayed: 100uF  VDC_V: 10V  [7343-31]  (hidden comment: CMP-0011720-2)
C92  ValueDisplayed: 1µF  [0805_HV]  (hidden comment: 0805YD105KAT2A)
C93  ValueDisplayed: 4.7µF  [0805_HV]  (hidden comment: CC0805ZRY5V6BB475)
C94  ValueDisplayed: 27pF  VDC_V: 50V  [0603]  (hidden comment: CMP-0007116-4)
D5  CMP-0002917-2  value Green  [QTLP630C_Green]
D6  CMP-0002917-2  value Green  [QTLP630C_Green]
D7  CMP-0002917-2  value Green  [QTLP630C_Green]
D8  CMP-0002917-2  value Green  [QTLP630C_Green]
F1  F0603E3R00FSTR  [0603]
J16  PJ-002AH  [CUI_PJ-002AH]
J17  1729160  [Phoenix_1729160]
J18  TSW-102-07-G-S  [TSW-102-07-G-S]
J20  TSW-102-07-G-S  [TSW-102-07-G-S]
J21  TSW-102-07-G-S  [TSW-102-07-G-S]
J23  TSW-102-07-G-S  [TSW-102-07-G-S]
J24  TSW-102-07-G-S  [TSW-102-07-G-S]
L1  ValueDisplayed: 10uH  [SRP5030T]  (hidden comment: SRP5030T-100M)
P2  TSW-103-07-G-D  [TSW-103-07-G-D]
Q1  DNBT8105-7  [SOT-23]
Q2  DNBT8105-7  [SOT-23]
Q3  DNBT8105-7  [SOT-23]
Q4  DNBT8105-7  [SOT-23]
R21  ValueDisplayed: 0  [0603]  (hidden comment: CMP-0025885-5)
R22  ValueDisplayed: 0  [0603]  (hidden comment: CMP-0025885-5)
R24  ValueDisplayed: 0  [0603]  (hidden comment: CMP-0025885-5)
R26  ValueDisplayed: 0  [0603]  (hidden comment: CMP-0025885-5)
R28  ValueDisplayed: 1.87k  [0603]  (hidden comment: RC0603FR-071K87L)
R30  ValueDisplayed: 4.99k  [0603]  (hidden comment: CRCW06034K99FKEAC)
R92  ValueDisplayed: 1.20k  [0603]  (hidden comment: RC0603FR-071K2L)
R93  ValueDisplayed: 100k  [0603]  (hidden comment: CRCW0603100KFKEA)
R94  ValueDisplayed: 2.40k  [0603]  (hidden comment: CMP-0023374-3)
R95  ValueDisplayed: 24.9k  [0603]  (hidden comment: CRCW060324K9FKEA)
R96  ValueDisplayed: 2.55k  [0603]  (hidden comment: RC0603FR-072K55L)
R97  ValueDisplayed: 0  [0603]  (hidden comment: CMP-0025885-5)
R98  ValueDisplayed: 2.40k  [0603]  (hidden comment: CMP-0023374-3)
R99  ValueDisplayed: 0  [0603]  (hidden comment: CMP-0025885-5)
R100  ValueDisplayed: 4.22k  [0603]  (hidden comment: CMP-0022451-4)
R101  ValueDisplayed: 2.40k  [0603]  (hidden comment: CMP-0023374-3)
R102  ValueDisplayed: 470  [0402]  (hidden comment: CMP-0026934-3)
R103  ValueDisplayed: 470  [0402]  (hidden comment: CMP-0026934-3)
R104  ValueDisplayed: 470  [0402]  (hidden comment: CMP-0026934-3)
R105  ValueDisplayed: 470  [0402]  (hidden comment: CMP-0026934-3)
R106  ValueDisplayed: 10.0k  [0603]  (hidden comment: CMP-0022746-5)
R108  ValueDisplayed: 2.49k  [0402]  (hidden comment: CRCW04022K49FKED)
R109  ValueDisplayed: 2.49k  [0402]  (hidden comment: CRCW04022K49FKED)
R110  ValueDisplayed: 2.49k  [0402]  (hidden comment: CRCW04022K49FKED)
R111  ValueDisplayed: 2.49k  [0402]  (hidden comment: CRCW04022K49FKED)
U6  LMR33620ARNXT  [RNX0012B]
U7  TL1963AQKTTRQ1  [KTT0005A_N]
U8  TL1963AQKTTRQ1  [KTT0005A_N]
U9  TL1963AQKTTRQ1  [KTT0005A_N]
U10  TPS74701DRCR  [DRC0010J]

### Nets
5V-36V: C63.1(+) C64.1 C65.1 C66.1 C67.1 F1.1 U6.2(VIN) U6.9(EN) U6.10(VIN)
GND: C50.2 C52.2 C53.2 C55.2 C57.2(-) C58.1 C59.1 C60.1 C61.1 C62.2 C63.2(-) C64.2 C65.2 C66.2 C67.2 C68.2 C70.2 C71.2 C73.2 C74.1 C75.1 C76.1 C77.1 C78.2 C80.2 C81.2 C83.2 C84.1 C85.1 C86.1 C87.2 C88.1 C91.2(-) C92.1 C93.2 C94.2 J16.2 J16.3 J17.6 J18.2 Q1.2(E) Q2.2(E) Q3.2(E) Q4.2(E) R30.1 R94.1 R95.1 R98.1 R101.1 U6.1(PGND) U6.6(AGND) U6.11(PGND) U7.3(GND) U7.6(TAB) U8.3(GND) U8.6(TAB) U9.3(GND) U9.6(TAB) U10.6(GND) U10.11(PAD)
USB_VBUS: J21.1
VDDIO: C84.2 J17.5 P2.2 P2.4 P2.6
1V1: C86.2 C87.1 C88.2 J24.1 R28.2 R106.1 R111.1 U10.9(OUT) U10.10(OUT)
1V8: C52.1 C53.1 C55.1 J23.1 P2.1 R92.2 R110.1 U7.4(OUT)
2V5: C70.1 C71.1 C73.1 J20.1 P2.3 R96.2 R109.1 U8.4(OUT)
3V3: C80.1 C81.1 C83.1 P2.5 R100.2 R102.2 R103.2 R104.2 R105.2 R108.1 U9.4(OUT)
5V: C50.1 C57.1(+) C58.2 C59.2 C60.2 C61.2 C68.1 C78.1 C85.2 C91.1(+) C92.2 C93.1 J17.1 J21.2 L1.2 R21.2 R22.2 R24.2 R26.2 R93.2 U7.2(IN) U8.2(IN) U9.2(IN) U10.1(IN) U10.2(IN) U10.4(BIAS)
5V-36V_jack: F1.2 J16.1 J18.1
VDD1P0: C77.2 J17.2 J24.2
VDDA1P8: J17.3 J23.2 R97.1 R99.1
VDDA1P8_AB: C75.2 R97.2
VDDA1P8_CD: C76.2 R99.2
VDDA2P5: C74.2 J17.4 J20.2
NetC56_1: C56.1 U6.4(BOOT)
NetC56_2: C56.2 L1.1 U6.3(NC) U6.12(SW)
NetC62_1: C62.1 U6.5(VCC)
NetC94_1: C94.1 U10.7(SS)
NetD5_1: D5.1(A) R102.1
NetD5_2: D5.2(K) Q1.3(C)
NetD6_1: D6.1(A) R103.1
NetD6_2: D6.2(K) Q2.3(C)
NetD7_1: D7.1(A) R104.1
NetD7_2: D7.2(K) Q3.3(C)
NetD8_1: D8.1(A) R105.1
NetD8_2: D8.2(K) Q4.3(C)
NetQ1_1: Q1.1(B) R108.2
NetQ2_1: Q2.1(B) R109.2
NetQ3_1: Q3.1(B) R110.2
NetQ4_1: Q4.1(B) R111.2
NetR21_1: R21.1 U7.1(~{SHDN})
NetR22_1: R22.1 U8.1(~{SHDN})
NetR24_1: R24.1 U9.1(~{SHDN})
NetR26_1: R26.1 U10.5(EN)
NetR28_1: R28.1 R30.2 U10.8(FB)
NetR92_1: R92.1 R94.2 U7.5(ADJ)
NetR93_1: R93.1 R95.2 U6.7(FB)
NetR96_1: R96.1 R98.2 U8.5(ADJ)
NetR100_1: R100.1 R101.2 U9.5(ADJ)
NetR106_2: R106.2 U10.3(PG)

Not connected (* = marked no-connect by the designer): U6 8(PG)*

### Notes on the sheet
- VDD1P8 Supply
- (near J16) Wide Vin Supply 5V-36V
- Wide-Vin Supply (5V-36V)
- Adjustable Supplies:
  3.3-V (Default) - 4.22K
  2.5-V - 2.56K
  1.8-V - 1.2k
- VDD2P5 Supply
- (near J23) Power Supply Selection
- VDD3P3 Supply
- VDD1P0 Supply
- Supply LED Indication
- (near C88) Close to LDO

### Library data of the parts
C50 C52 C68 C70 C78 C80 = CMP-0009155-2: CAP, CERM, 10 uF, 25 V, +/- 20%, X7R, AEC-Q200 Grade 1, 1210; PartNumber: CGA6P1X7R1E106M250AC; Manufacturer: TDK; Polarized: N; Value: 10uF; U/M: EA; Cap_F: 10µF; Value1: Unknown; TaMin_C: -55°C; TaMax_C: 125°C; Cap_Case: 1210; AEC Category: Q200; AEC Qualified: Y; AEC Grade: 1; SizeAreaWB_mm2: 14.7; SizeZ_mm: 2.8; SizeX_mm: 3.2; SizeY_mm: 2.5; SizeArea_mm2: 8
C53 C71 C81 = CMP-0007676-2: CAP, CERM, 1 uF, 16 V, +/- 10%, X5R, 0805; Manufacturer: AVX; TaMin_C: -55°C; ESR_ohm: 0.012; Polarized: N; SizeAreaWB_mm2: 6.75; Value1: 0.012 ohm; U/M: EA; Value: 1uF; TaMax_C: 85°C; SizeZ_mm: 1.45; SizeX_mm: 2; SizeY_mm: 1.25; Cap_Case: 0805; SizeArea_mm2: 2.5; Cap_F: 1µF; AEC Category: Q200
C55 C73 C83 = CMP-0006324-2: CAP, CERM, 0.01 uF, 50 V, +/- 10%, X7R, AEC-Q200 Grade 1, 0402; PartNumber: CGA2B3X7R1H103K050BB; Manufacturer: TDK; Polarized: N; Value: 0.01uF; U/M: EA; Cap_F: 10nF; ESR_ohm: 0.333065; Value1: 0.333065 ohm; IRMS_A: 323.373mA; TaMin_C: -55°C; TaMax_C: 125°C; AEC Category: Q200; AEC Qualified: Y; AEC Grade: 1; SizeAreaWB_mm2: 3; SizeZ_mm: 0.6; SizeY_mm: 0.5
C56 = CMP-0006356-2: CAP, CERM, 0.1 uF, 50 V, +/- 10%, X7R, AEC-Q200 Grade 1, 0402; Manufacturer: MuRata; TaMin_C: -55°C; Polarized: N; SizeAreaWB_mm2: 3; Value1: Unknown; U/M: EA; Value: 0.1uF; TaMax_C: 125°C; SizeZ_mm: 0.6; SizeX_mm: 1; SizeY_mm: 0.5; Value2: 50V; AEC Qualified: Y; Cap_F: 100nF; AEC Category: Q200
C57 = CMP-0011752-2: CAP, TA, 220 µF, 6.3 V, +/- 10%, 0.7 ohm, SMD; Manufacturer: Kemet; Polarized: Y; CompType: Capacitor; Value: 220uF; U/M: EA; Cap_F: 0.00022; Tolerance_%: 10; Value1: 0.7 ohm; VDC_V: 6.3; Value2: 6.3V; ESR_ohm: 0.7; IRMS_A: 0.463; TaMin_C: -55; TaMax_C: 125; Cap_Case: D
C58 C61 C88 = CMP-0006850-4: CAP, CERM, 0.01 uF, 50 V, +/- 5%, X7R, 0603; PartNumber: C0603C103J5RACTU; Manufacturer: Kemet; Polarized: N; Value: 0.01uF; U/M: EA; Value1: Unknown; TaMin_C: -55°C; TaMax_C: 125°C; SizeAreaWB_mm2: 4.68; SizeZ_mm: 1; SizeX_mm: 1.6; SizeY_mm: 0.8; SizeArea_mm2: 1.28; AEC Category: Q200
C59 = CMP-0006303-2: CAP, CERM, 100 pF, 50 V, +/- 5%, C0G/NP0, 0402; PartNumber: CC0402JRNPO9BN101; Manufacturer: Yageo America; Polarized: N; Value: 100pF; U/M: EA; Value1: Unknown; TaMin_C: -55°C; TaMax_C: 125°C; SizeAreaWB_mm2: 3; SizeZ_mm: 0.6; SizeX_mm: 1; SizeY_mm: 0.5; AEC Category: Q200
C60 C85 C86 = CMP-0093118-1: Cap Ceramic 10uF 35V X7R 20% Pad SMD 1206 Soft Termination 125C Low ESR Automotive T/R; Manufacturer: Taiyo Yuden; AEC Qualified: Yes; Cap_F: 10µF; SizeZ_mm: 1.9mm; TempCo: 15%; AEC Grade: Grade 1; Value: 10µF
C62 = CMP-0007067-4: CAP, CERM, 1 uF, 35 V, +/- 10%, X7R, AEC-Q200 Grade 1, 0603; Manufacturer: TDK; TaMin_C: -55°C; ESR_ohm: 5.522m; Polarized: N; SizeAreaWB_mm2: 4.68; Value1: 0.005522 ohm; U/M: EA; Value: 1uF; TaMax_C: 125°C; SizeZ_mm: 1; SizeX_mm: 1.6; SizeY_mm: 0.8; Value2: 35V; SizeArea_mm2: 1.28; AEC Qualified: Y; IRMS_A: 2.21617A; AEC Category: Q200
C63 = CMP-0011279-3: CAP, AL, 100 uF, 50 V, +/- 20%, SMD; Manufacturer: Chemi-Con; TaMin_C: -40°C; Polarized: Y; SizeAreaWB_mm2: 106.09; Value1: Unknown; U/M: EA; Value: 100uF; TaMax_C: 105°C; SizeZ_mm: 10; SizeX_mm: 8.3; Cap_Case: HA0; Value2: 50V; SizeArea_mm2: 68.89; CompType: Capacitor; Cap_F: 100µF; IRMS_A: 230mA; AEC Category: Q200
C64 C66 = CMP-0009162-2: CAP, CERM, 4.7 uF, 50 V, +/- 10%, X7R, AEC-Q200 Grade 1, 1210; Manufacturer: TDK; TaMin_C: -55°C; ESR_ohm: 3.166m; Polarized: N; SizeAreaWB_mm2: 14.7; Value1: 0.003166 ohm; U/M: EA; Value: 4.7uF; TaMax_C: 125°C; SizeZ_mm: 2.8; SizeX_mm: 3.2; SizeY_mm: 2.5; Value2: 50V; SizeArea_mm2: 8; AEC Qualified: Y; Cap_F: 4.7µF; IRMS_A: 4.13311A; AEC Grade: 1; AEC Category: Q200
C65 C67 = CMP-0007094-5: CAP, CERM, 0.22 uF, 50 V, +/- 10%, X7R, AEC-Q200 Grade 1, 0603; Manufacturer: TDK; TaMin_C: -55°C; ESR_ohm: 0.021699; Polarized: N; SizeAreaWB_mm2: 4.68; Value1: 0.021699 ohm; U/M: EA; Value: 0.22uF; TaMax_C: 125°C; SizeZ_mm: 1; SizeX_mm: 1.6; SizeY_mm: 0.8; Value2: 50V; SizeArea_mm2: 1.28; AEC Qualified: Y; IRMS_A: 1.12496A; AEC Category: Q200
C74-C77 C84 = CMP-0009154-2: CAP, CERM, 22 uF, 16 V, +/- 20%, X7R, AEC-Q200 Grade 1, 1210; PartNumber: CGA6P1X7R1C226M250AC; Manufacturer: TDK; Polarized: N; Value: 22uF; U/M: EA; Cap_F: 22µF; ESR_ohm: 2.582m; Value1: 0.002582 ohm; IRMS_A: 4.57562A; TaMin_C: -55°C; TaMax_C: 125°C; AEC Category: Q200; AEC Qualified: Y; AEC Grade: 1; SizeAreaWB_mm2: 14.7; SizeZ_mm: 2.8; SizeX_mm: 3.2; SizeY_mm: 2.5; SizeArea_mm2: 8
C87 = CMP-0007110-5: CAP, CERM, 0.1 uF, 16 V, +/- 10%, X7R, 0603; Manufacturer: Samsung Electro-Mechanics; Polarized: N; Value: 0.1uF; U/M: EA; Value1: Unknown; TaMin_C: -55°C; TaMax_C: 125°C; SizeAreaWB_mm2: 4.68; SizeZ_mm: 1; SizeX_mm: 1.6; SizeY_mm: 0.8; SizeArea_mm2: 1.28; AEC Category: Q200
C91 = CMP-0011720-2: CAP, TA, 100 uF, 10 V, +/- 20%, 0.1 ohm, SMD; PartNumber: 593D107X0010D2TE3; Manufacturer: Vishay-Sprague; Polarized: Y; CompType: Capacitor; Value: 100uF; U/M: EA; Cap_F: 100µF; Value1: 0.1 ohm; ESR_ohm: 0.1; IRMS_A: 1.22A; TaMin_C: -55°C; TaMax_C: 125°C; Cap_Case: D; SizeAreaWB_mm2: 58.59; SizeZ_mm: 3.1; SizeX_mm: 7.3; SizeY_mm: 4.3; SizeArea_mm2: 31.39; AEC Category: Q200
C92 = CMP-0007676-2: CAP, CERM, 1 µF, 16 V, +/- 10%, X5R, 0805; Manufacturer: AVX; Polarized: N; CompType: Capacitor; Value: 1uF; U/M: EA; Cap_F: 0.000001; Tolerance_%: 10; ESR_ohm: 0.012; Value1: 0.012 ohm; VDC_V: 16; Value2: 16V; TaMin_C: -55; TaMax_C: 85; Cap_Case: 0805
C93 = CMP-0007960-1: CAP, CERM, 4.7 µF, 10 V, +80/-20%, Y5V, 0805; Manufacturer: Yageo America; Polarized: N; CompType: Capacitor; Value: 4.7uF; U/M: EA; Cap_F: 0.0000047; Tolerance_%: 80; Value1: Unknown; VDC_V: 10; Value2: 10V; TaMin_C: -30; TaMax_C: 85; Cap_Case: 0805
C94 = CMP-0007116-4: CAP, CERM, 27 pF, 50 V, +/- 1%, C0G/NP0, 0603; PartNumber: CL10C270FB8NNNC; Manufacturer: Samsung Electro-Mechanics; Polarized: N; Value: 27pF; U/M: EA; Value1: Unknown; TaMin_C: -55°C; TaMax_C: 125°C; SizeAreaWB_mm2: 4.68; SizeZ_mm: 1; SizeX_mm: 1.6; SizeY_mm: 0.8; SizeArea_mm2: 1.28; AEC Category: Q200
D5-D8 = CMP-0002917-2: as LD1 on sheet HSDC106B_EVM_DP83561_64p_Straps
F1 = CMP-0003588-3: Fuse, 3 A, 32 VDC, SMD; Manufacturer: AVX; Irating_A: 3A; SizeAreaWB_mm2: 4.68; SizeZ_mm: 1; SizeX_mm: 1.6; SizeY_mm: 0.8; SizeArea_mm2: 1.28; VDC_V: 32V; Rtyp_Ohm: 0.03
J16 = CMP-0078270-1: DC POWER JACK, R/A, TH; Manufacturer: CUI Inc.; Gender: Female; Cert_UL: Y; Current_A: 5A; Voltage_V: 24V; Green_REACh: Incomplete; Green_Lifecycle: Not Set
J17 = CMP-0055492-1: Terminal Block, 6x1, 5.08mm, Th; Manufacturer: Phoenix Contact; CT: TRUE; CNHeader: FALSE
J18 J20 J21 J23 J24 = CMP-0075405-3: as J29 on sheet HSDC106B_EVM_DP83561_64p_Straps
L1 = CMP-0056947-1: Inductor, Shielded, Ferrite, 10 uH, 2.75 A, 0.128 ohm, SMD; Manufacturer: Bourns; Isat: 3.5A @ 20% inductance drop; Irms: 2.75A @ 40C rise; Green_Lifecycle: Active; SizeAreaWB_mm2: 59.2; DCR_ohm: 0.128; Green_REACh: Passed; Value: 10uH; Imax_A: 2.75A; SizeZ_mm: 3; SizeX_mm: 6; SizeY_mm: 5.4; SizeArea_mm2: 32.4; Ind_H: 10µH; AEC Category: Q200
P2 = CMP-0075406-2: Header, 100mil, 3x2, Gold, TH; Manufacturer: Samtec; Pitch_mm: 2.54; Cert_VDE: N; Gender: Male; Cert_CSA: Y; Voltage_V: 550V; Green_REACh: Passed; Current_A: 6.3A; Green_Lifecycle: Active; Row_Count: 2
Q1-Q4 = CMP-0064871-1: Transistor, NPN, 60 V, 1 A, AEC-Q101, SOT-23; Manufacturer: Diodes Inc.; TaMin_C: -55°C; HfeMax: 300; Green_Lifecycle: Not Set; SizeAreaWB_mm2: 14; Green_REACh: Incomplete; Value1: 1 A; Vceo_V: 60V; U/M: EA; Value: 60 V; TaMax_C: 150°C; IcRated_A: 1A; SizeZ_mm: 1.1; SizeX_mm: 2.5; SizeY_mm: 3; SizeArea_mm2: 7.5; CompType: BJT; PNP: 0; AEC Qualified: Y; NPN: 1; Vcesat1_V: 250mV; AEC Category: Q101
R21 R22 R24 R26 R97 R99 = CMP-0025885-5: RES, 0, 5%, 0.1 W, 0603; PartNumber: RC0603JR-070RL; Manufacturer: Yageo; Value: 0; Value_Code: 0000; Power_W: 100mW; Value2: 0.1W; VDC_V: 75V; TempCo: 200 ppm/C; EIA_Code: E24; SizeX_mm: 1.6; SizeZ_mm: 1; SizeArea_mm2: 1.28; AEC Qualified: N; AEC Category: Q200; SizeY_mm: 0.8; SizeAreaWB_mm2: 4.68
R28 = CMP-0022891-5: RES, 1.87 k, 1%, 0.1 W, 0603; Manufacturer: Yageo; Power_W: 100mW; TempCo: 100 ppm/C; Value_Code: 1k87; Value: 1.87k; EIA_Code: E96; SizeX_mm: 1.6; SizeY_mm: 0.8; SizeZ_mm: 1; Value2: 0.1W; SizeArea_mm2: 1.28; AEC Qualified: N; VDC_V: 75V; AEC Category: Q200; SizeAreaWB_mm2: 4.68
R30 = CMP-0082533-1: RES, 4.99 k, 1%, 0.1 W, 0603; Manufacturer: Vishay-Dale; Power_W: 100mW; TempCo: 100 ppm/C; SizeAreaWB_mm2: 4.68; Value_Code: 4k99; Value: 4.99k; EIA_Code: E96; SizeX_mm: 1.6; SizeY_mm: 0.8; SizeZ_mm: 1; Value2: 0.1W; SizeArea_mm2: 1.28; AEC Qualified: N; VDC_V: 75V; AEC Category: Q200
R92 = CMP-0022874-5: RES, 1.20 k, 1%, 0.1 W, 0603; Manufacturer: Yageo; Power_W: 100mW; TempCo: 100 ppm/C; Value_Code: 1k20; Value: 1.20k; Res_ohm: 1.2k; SizeX_mm: 1.6; SizeY_mm: 0.8; SizeZ_mm: 1; Value2: 0.1W; SizeArea_mm2: 1.28; AEC Qualified: N; VDC_V: 75V; AEC Category: Q200; SizeAreaWB_mm2: 4.68
R93 = CMP-0021990-4: RES, 100 k, 1%, 0.1 W, AEC-Q200 Grade 0, 0603; Manufacturer: Vishay-Dale; Power_W: 100mW; TempCo: 100 ppm/C; Value: 100k; EIA_Code: E96; SizeX_mm: 1.6; SizeY_mm: 0.8; SizeZ_mm: 1; Value2: 0.1W; SizeArea_mm2: 1.28; AEC Qualified: Y; VDC_V: 75V; AEC Category: Q200; AEC Grade: 0
R94 R98 R101 = CMP-0023374-3: RES, 2.40 k, 0.1%, 0.1 W, AEC-Q200 Grade 0, 0603; PartNumber: ERA-3AEB242V; Manufacturer: Panasonic; Value: 2.40k; Res_ohm: 2.4k; Value_Code: 2k40; Power_W: 100mW; Value2: 0.1W; VDC_V: 75V; TempCo: 25 ppm/C; EIA_Code: E192; U/M: EA; AEC Category: Q200; AEC Qualified: Y; AEC Grade: 0; SizeX_mm: 1.6; SizeY_mm: 0.8; SizeZ_mm: 1; SizeArea_mm2: 1.28
R95 = CMP-0022237-4: RES, 24.9 k, 1%, 0.1 W, AEC-Q200 Grade 0, 0603; Manufacturer: Vishay-Dale; Power_W: 100mW; TempCo: 100 ppm/C; Value_Code: 24k9; Value: 24.9k; EIA_Code: E96; SizeX_mm: 1.6; SizeY_mm: 0.8; SizeZ_mm: 1; Value2: 0.1W; SizeArea_mm2: 1.28; AEC Qualified: Y; VDC_V: 75V; AEC Category: Q200; AEC Grade: 0
R96 = CMP-0022992-5: RES, 2.55 k, 1%, 0.1 W, 0603; Manufacturer: Yageo; Power_W: 100mW; TempCo: 100 ppm/C; Value_Code: 2k55; Value: 2.55k; EIA_Code: E96; SizeX_mm: 1.6; SizeY_mm: 0.8; SizeZ_mm: 1; Value2: 0.1W; SizeArea_mm2: 1.28; AEC Qualified: N; VDC_V: 75V; AEC Category: Q200; SizeAreaWB_mm2: 4.68
R100 = CMP-0022451-4: RES, 4.22 k, 1%, 0.1 W, AEC-Q200 Grade 0, 0603; PartNumber: CRCW06034K22FKEA; Manufacturer: Vishay-Dale; Value: 4.22k; Value_Code: 4k22; Power_W: 100mW; Value2: 0.1W; VDC_V: 75V; TempCo: 100 ppm/C; EIA_Code: E96; AEC Category: Q200; AEC Qualified: Y; AEC Grade: 0; SizeX_mm: 1.6; SizeY_mm: 0.8; SizeZ_mm: 1; SizeArea_mm2: 1.28
R102-R105 = CMP-0026934-3: RES, 470, 5%, 0.063 W, AEC-Q200 Grade 0, 0402; PartNumber: CRCW0402470RJNED; Manufacturer: Vishay-Dale; Value: 470; Value_Code: 470R; Power_W: 63mW; Value2: 0.063W; VDC_V: 50V; TempCo: 200 ppm/C; EIA_Code: E24; SizeX_mm: 1; SizeY_mm: 0.5; SizeZ_mm: 0.6; AEC Qualified: Y; AEC Category: Q200; AEC Grade: 0
R106 = CMP-0022746-5: RES, 10.0 k, 1%, 0.1 W, 0603; PartNumber: RC0603FR-0710KL; Manufacturer: Yageo; Value: 10.0k; Res_ohm: 10k; Value_Code: 10k0; Power_W: 100mW; Value2: 0.1W; VDC_V: 75V; TempCo: 100 ppm/C; EIA_Code: E96; SizeX_mm: 1.6; SizeY_mm: 0.8; SizeZ_mm: 1; SizeArea_mm2: 1.28; AEC Qualified: N; AEC Category: Q200; SizeAreaWB_mm2: 4.68
R108-R111 = CMP-0026237-2: as R151 on sheet HSDC106B_EVM_DP83561_64p_Straps
U6 = CMP-0081171-4: 3.8-V to 36-V 2-A Synchronous Step-Down Voltage Regulator, RNX0012B (VQFN-HR-12); Manufacturer: Texas Instruments; Alternate PartNumber: LMR33620ARNXR; AEC Qualified: N; SizeZ_mm: 0.9; SizeAreaWB_mm2: 12.0; AEC Category: Q200; SizeX_mm: 2.0; SizeY_mm: 3.0; SizeArea_mm2: 6.0; Rating: Catalog; CompType: IC
U7-U9 = CMP-0036893-1: Single Output Fast Transient Response LDO, 1.5 A, Adjustable 1.21 to 20 V Output, 2.1 to 20 V Input, 5-pin DDPAK (KTT), -40 to 125 degC, Green (RoHS & no Sb/Br); Manufacturer: Texas Instruments; Vin(Min)(V): 2.1; SubFamily: Single Channel LDO; Vdo(Typ)(mV): 340; Iq(Typ)(mA): 1; Vout Adj(Min)(V): 1.21; Vin(Max)(V): 20; Iout(Max)(A): 1.5
U10 = CMP-0036362-5: Single Output LDO, 500mA, Adj. (0.8 to 3.6V), Programmable Soft-Start, DRC0010J (VSON-10); Manufacturer: Texas Instruments; Vout Adj(Min)(V): 0.8; Rating: Catalog; Iq(Typ)(mA): 1; CompType: IC; Accuracy(%): 2; SizeX_mm: 3; Vdo(Typ)(mV): 50; Vin(Max)(V): 5.5; AEC Category: Q200; Vout Adj(Max)(V): 3.6; Power Good: TRUE; AEC Qualified: N; SizeAreaWB_mm2: 16; SizeArea_mm2: 9; Iout(Max)(A): 0.5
